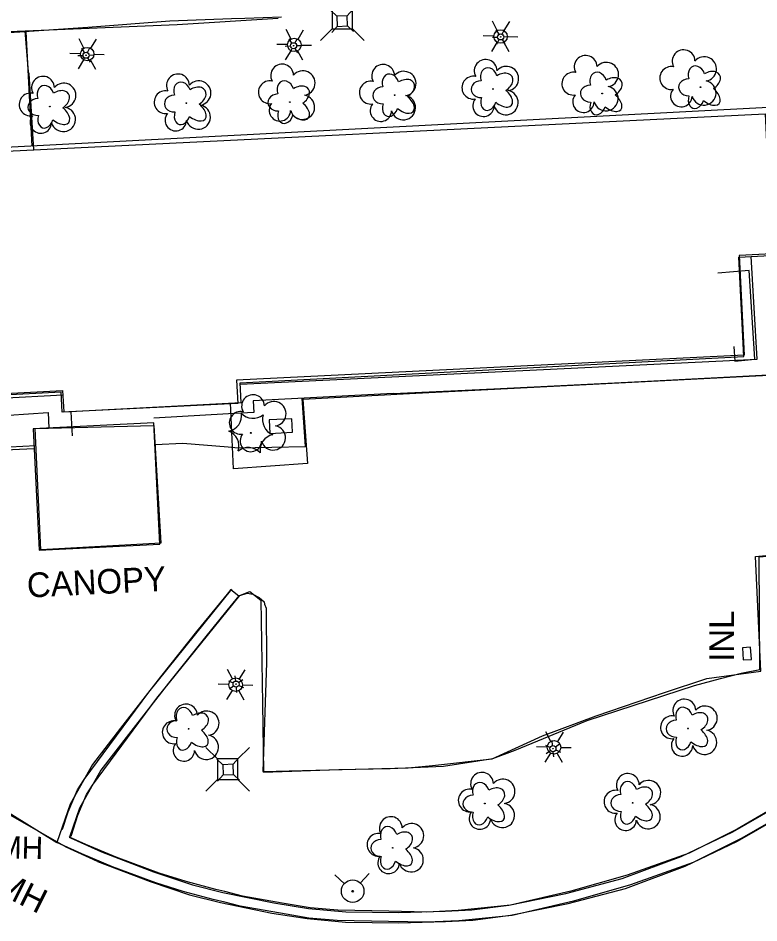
# Model space of a CAD drawing. Extents: x 588843 to 2552415, y 180129 to 269402.
# Drawn here: x 594920.9 to 595101, y 184366.5 to 184586.7 of the extents above; entities that cross this region are included whole.
import ezdxf

# ---------------------------------------------------------------- set-up
doc = ezdxf.new("R2010")
doc.units = 0
for name, color, linetype in [('E_BLD', 7, 'Continuous'), ('E_BLD_HvyDash', 7, 'Continuous'), ('E_BLD_Text', 7, 'Continuous'), ('E_DWY', 7, 'Continuous'), ('E_LAND_Vegetation', 7, 'Continuous'), ('E_LTG', 7, 'Continuous'), ('E_PATH_Sidewalk', 7, 'Continuous'), ('E_RDWY_C_and_G', 7, 'Continuous'), ('E_UTL_AG_Bold', 7, 'Continuous'), ('E_UTL_MH', 7, 'Continuous'), ('E_UTL_MH_Text', 7, 'Continuous'), ('E_UTL_SAN', 7, 'Continuous'), ('E_UTL_WHydrant', 7, 'Continuous'), ('Level 11', 7, 'Continuous'), ('Level 12', 7, 'Continuous'), ('Level 14', 7, 'Continuous'), ('Level 15', 7, 'Continuous'), ('Level 17', 7, 'Continuous'), ('Level 18', 7, 'Continuous'), ('Level 21', 7, 'Continuous')]:
    doc.layers.add(name, color=color, linetype=linetype)

# ---------------------------------------------------------------- blocks, each defined once
blk = doc.blocks.new('MH')
at = {"layer": 'E_UTL_MH'}
for radius in [5, 4, 1.5]:
    blk.add_circle((0, 0), radius, dxfattribs=at)
blk.add_text('MH', height=10.8, dxfattribs=at).set_placement((10, -5.4))
blk = doc.blocks.new('MHT_3')
at = {"layer": 'E_UTL_MH_Text'}
blk.add_text('MH', height=39.37, dxfattribs=at).set_placement((-32.2, -19.7))
blk = doc.blocks.new('LPOL_4')
at = {"layer": 'E_LTG'}
for p, q in [((-13.1, 0), (-4.9, 0)), ((-2.5, 4.3), (-6.6, 11.4)), ((2.5, 4.3), (6.6, 11.4)), ((4.9, 0), (13.1, 0)), ((-6.6, -11.4), (-2.5, -4.3)), ((6.6, -11.4), (2.5, -4.3))]:
    blk.add_line(p, q, dxfattribs=at)
for radius in [4.92, 4.92, 4.92, 0.41]:
    blk.add_circle((0, 0), radius, dxfattribs=at)
blk = doc.blocks.new('PED_3')
at = {"layer": 'E_UTL_AG_Bold'}
for p, q in [((-8.2, 8.2), (-17.5, 17.5)), ((8.2, 8.2), (17.5, 17.5)), ((-8.2, -8.2), (-17.5, -17.5)), ((8.2, -8.2), (17.5, -17.5))]:
    blk.add_line(p, q, dxfattribs=at)
blk.add_lwpolyline([(-8.2, -8.2), (8.2, -8.2), (8.2, 8.2), (-8.2, 8.2)], close=True, dxfattribs=at)
blk = doc.blocks.new('DTRE_4')
at = {"layer": 'E_LAND_Vegetation'}
blk.add_circle((-0.6, 0), 0.601, dxfattribs=at)
for centre, major_axis, ratio in [((-6.1, 17.5), (4.5, -16.3), 0.782863), ((13.3, 9), (-17.3, -9.6), 0.691916), ((-19.3, 0.5), (16.2, -0.4), 0.832022), ((-8.2, -17.2), (5.9, 15.9), 0.716896), ((11.6, -12.2), (-16.4, 15), 0.560249)]:
    blk.add_ellipse(centre, major_axis=major_axis, ratio=ratio, start_param=1.570796, end_param=4.712389, dxfattribs=at)
blk = doc.blocks.new('HYD_3')
at = {"layer": 'E_UTL_WHydrant'}
for p, q in [((-12.6, 12.6), (-27.3, 27.3)), ((12.6, 12.6), (27.3, 27.3))]:
    blk.add_line(p, q, dxfattribs=at)
for radius in [18, 1.38]:
    blk.add_circle((0, 0), radius, dxfattribs=at)
blk = doc.blocks.new('CTRE_4')
at = {"layer": 'E_LAND_Vegetation'}
blk.add_circle((0, 0), 0.733, dxfattribs=at)
for centre, start, end in [((-39.3, 29.4), 280.2067, 5.9716), ((5.9, 49), 220.2113, 305.9762), ((45.4, 19.3), 160.2113, 245.9762), ((-45.4, -19.3), 340.2113, 65.9762), ((39.5, -29.6), 100.2511, 185.9272), ((-5.9, -49), 40.2113, 125.9762)]:
    blk.add_arc(centre, 25.8, start, end, dxfattribs=at)
blk = doc.blocks.new('CANOPY_1')
at = {"layer": 'E_BLD_Text'}
blk.add_text('CANOPY', height=39.37, dxfattribs=at).set_placement((-106.7, -19.7))

msp = doc.modelspace()

# ---------------------------------------------------------------- linework, layer by layer
at = {"layer": 'E_BLD'}
msp.add_lwpolyline([(594931.34, 184495.6), (594915.76, 184494.83), (594915.75, 184495.15), (594887.49, 184493.76), (594884.59, 184552.69), (594913.65, 184554.12), (594912.97, 184554.09), (594984.08, 184557.57), (595102.54, 184563.39), (595104.21, 184529.31), (595096.26, 184528.92), (595097.45, 184504.62), (594974.02, 184498.56), (594974.3, 184492.84), (594931.58, 184490.74)], close=True, dxfattribs=at)
at = {"layer": 'E_BLD_HvyDash'}
for points in [[(594955.54, 184458.88), (594926.41, 184457.28), (594925.02, 184486.76), (594953.9, 184487.5)], [(594953.9, 184487.5), (594955.54, 184458.88)]]:
    msp.add_lwpolyline(points, dxfattribs=at)
at = {"layer": 'E_DWY'}
for points in [[(594853.87, 184578.66), (594856.32, 184579.18), (594875.82, 184580.94), (594916.75, 184583.36), (594959.55, 184585.14), (594984.11, 184586.69)], [(595171.81, 184472.65), (595167.63, 184473.03), (595154.87, 184476.19), (595146.63, 184479.73), (595142.36, 184483.18), (595140.93, 184485.01), (595139.64, 184487.73), (595138.95, 184488.95), (595138.65, 184498.88), (595121.13, 184497.84), (595120.87, 184500.58), (595076.53, 184498.31), (595017.63, 184495.3), (594990.15, 184493.86), (594991.23, 184478.27), (594973.21, 184476.95), (594972.49, 184493.05)], [(594934.07, 184485.02), (594933.77, 184490.85)], [(594881.64, 184488.04), (594882.74, 184475.24), (594890.54, 184477.1), (594890.22, 184480.27), (594909.31, 184481.87), (594925.21, 184482.68)], [(594974.75, 184446.16), (594976.54, 184446.68), (594977.93, 184446.5), (594979.53, 184445.64), (594980.68, 184444.6), (594980.83, 184444.05), (594981.16, 184443.03), (594981.25, 184429.77), (594980.42, 184403.34), (595015.75, 184404.22), (595021.63, 184404.73), (595036.16, 184406.41), (595048.39, 184412.02), (595061.45, 184416.88), (595078.12, 184422.57), (595088.4, 184425.96), (595101.51, 184427.72), (595100.2, 184455.68), (595119.69, 184457.51)], [(594931.59, 184389.19), (594931.65, 184389.24), (594933.03, 184393.52), (594935.28, 184398.87), (594936.9, 184401.38), (594952.64, 184422.65), (594972.81, 184447.72)], [(594933.3, 184387.36), (594933.83, 184387.85), (594935.37, 184392.65), (594937.5, 184397.7), (594938.96, 184399.96), (594954.62, 184421.12), (594974.75, 184446.16)]]:
    msp.add_lwpolyline(points, dxfattribs=at)
at = {"layer": 'E_PATH_Sidewalk'}
for points in [[(594922.53, 184583.6), (594923.28, 184573.61), (594923.48, 184573.24), (594924.59, 184554.66)], [(595094.93, 184506.72), (595095.17, 184503.17), (595100.02, 184503.66), (595098.68, 184525.26), (595091.02, 184524.64)]]:
    msp.add_lwpolyline(points, dxfattribs=at)
at = {"layer": 'E_RDWY_C_and_G'}
for points in [[(594840.99, 184416.47), (594853.52, 184416.52), (594859.86, 184416.05), (594867.1, 184415.1), (594873.59, 184413.68), (594882.4, 184411.05), (594888.77, 184408.67), (594896.76, 184405.03), (594901.36, 184402.7), (594932.46, 184384.96), (594940.08, 184381.5)], [(594941.11, 184383.77), (594953.78, 184378.89), (594963.26, 184375.72), (594970.64, 184373.86), (594983.05, 184371.31), (594991.5, 184369.98), (595000.61, 184369.17), (595013.47, 184368.96), (595024.75, 184369.29), (595031.2, 184369.64), (595040.25, 184370.8), (595054.06, 184373.61), (595067.8, 184377.25), (595082.11, 184382.58), (595094.67, 184388.61), (595108.85, 184396.75)], [(594940.21, 184381.44), (594952.94, 184376.53), (594962.55, 184373.32), (594970.08, 184371.43), (594982.6, 184368.85), (594991.19, 184367.49), (595000.48, 184366.67), (595013.49, 184366.46), (595024.85, 184366.79), (595031.43, 184367.15), (595040.66, 184368.33), (595054.63, 184371.17), (595068.56, 184374.86), (595083.09, 184380.28), (595095.84, 184386.39), (595110.09, 184394.58)], [(594933.3, 184387.36), (594933.6, 184387.18), (594941.11, 184383.77)]]:
    msp.add_lwpolyline(points, dxfattribs=at)
at = {"layer": 'Level 11'}
for points in [[(595163.36, 184448.74), (595157.09, 184440.22), (595149.33, 184431.32), (595142.04, 184423.12), (595133.82, 184415.06), (595127.52, 184409.82), (595118.72, 184402.98), (595108.04, 184396.38), (595095.75, 184389.27), (595084.08, 184383.45), (595069.02, 184378.08), (595055.31, 184374.2), (595040.62, 184370.76), (595027.88, 184369.5), (595020.28, 184369.11), (595011.01, 184369.29)], [(595165.37, 184447.26), (595159.04, 184438.66), (595151.2, 184429.67), (595143.85, 184421.39), (595135.49, 184413.21), (595129.09, 184407.87), (595120.15, 184400.92), (595109.32, 184394.23), (595096.93, 184387.07), (595085.06, 184381.14), (595069.78, 184375.7), (595055.94, 184371.78), (595041.03, 184368.29), (595028.06, 184367), (595020.32, 184366.61), (595010.96, 184366.79)], [(594907.81, 184399.6), (594915.61, 184395.1), (594930.27, 184386.02)], [(594971.15, 184374.06), (594968.95, 184374.6), (594961.73, 184376.51), (594955.19, 184378.6), (594944.7, 184382.47), (594937.33, 184385.53), (594933.37, 184387.34)], [(594971.13, 184371.49), (594968.33, 184372.18), (594961.03, 184374.11), (594954.38, 184376.23), (594943.79, 184380.14), (594936.33, 184383.24), (594930.27, 184386.02)], [(595011.01, 184369.29), (594998.63, 184369.55), (594991.91, 184370.13), (594985.1, 184371.25), (594975.44, 184373), (594971.15, 184374.06)], [(595010.96, 184366.79), (594998.49, 184367.05), (594991.59, 184367.65), (594984.67, 184368.79), (594974.91, 184370.56), (594971.13, 184371.49)]]:
    msp.add_lwpolyline(points, dxfattribs=at)
at = {"layer": 'Level 12'}
for points in [[(595103.37, 184564.96), (594885.16, 184553.5)], [(594888.17, 184493.75), (594931.68, 184496.04), (594931.95, 184490.86), (594975.12, 184493.12), (594974.87, 184497.91), (595097.42, 184504.34), (595096.15, 184528.53), (595105.26, 184529.01), (595103.37, 184564.96)], [(594955.37, 184458.65), (594953.91, 184488.17), (594924.5, 184486.71), (594925.96, 184457.2), (594955.37, 184458.65)]]:
    msp.add_lwpolyline(points, dxfattribs=at)
at = {"layer": 'Level 14'}
for p, q in [((595037.41, 184583.64), (595036.21, 184585.94)), ((595039.11, 184583.63), (595040.48, 184585.86)), ((594987.24, 184581.59), (594986.04, 184583.89)), ((594988.94, 184581.58), (594990.3, 184583.81)), ((594936.87, 184579.36), (594935.67, 184581.67)), ((594938.57, 184579.36), (594939.93, 184581.59)), ((595036.58, 184582.27), (595033.97, 184582.35)), ((595039.85, 184582.18), (595042.37, 184582.12)), ((594986.4, 184580.23), (594983.8, 184580.3)), ((594987.16, 184578.73), (594985.79, 184576.54)), ((594988.79, 184578.69), (594990.04, 184576.51)), ((594989.67, 184580.13), (594992.19, 184580.07)), ((595037.33, 184580.78), (595035.97, 184578.59)), ((595038.97, 184580.74), (595040.21, 184578.56)), ((594936.03, 184578), (594933.43, 184578.07)), ((594936.79, 184576.51), (594935.43, 184574.32)), ((594938.43, 184576.46), (594939.67, 184574.29)), ((594939.31, 184577.91), (594941.83, 184577.84)), ((594973, 184425.86), (594971.8, 184428.16)), ((594974.7, 184425.85), (594976.06, 184428.08)), ((594972.16, 184424.5), (594969.56, 184424.57)), ((594972.92, 184423.01), (594971.55, 184420.82)), ((594974.55, 184422.96), (594975.8, 184420.78)), ((594975.43, 184424.4), (594977.95, 184424.34)), ((595050.42, 184410.63), (595049.22, 184412.93)), ((595052.12, 184410.62), (595053.48, 184412.85)), ((595049.58, 184409.27), (595046.98, 184409.34)), ((595052.85, 184409.18), (595055.37, 184409.11)), ((595050.34, 184407.77), (595048.97, 184405.58)), ((595051.97, 184407.73), (595053.22, 184405.55))]:
    msp.add_line(p, q, dxfattribs=at)
for centre in [(595038.21, 184582.21), (594988.03, 184580.16), (594937.67, 184577.93), (594973.79, 184424.43), (595051.21, 184409.2)]:
    msp.add_circle(centre, 1.64, dxfattribs=at)
at = {"layer": 'Level 15'}
msp.add_lwpolyline([(595097.24, 184430.45), (595099.23, 184430.58), (595099.03, 184433.57), (595097.04, 184433.44), (595097.24, 184430.45)], dxfattribs=at)
at = {"layer": 'Level 17'}
for points in [[(594972.73, 184586.48), (594957.77, 184585.95), (594937.84, 184584.4), (594923.51, 184583.44), (594922.71, 184583.38)], [(594984.94, 184586.91), (594976.02, 184586.59), (594972.73, 184586.48)], [(594922.71, 184583.38), (594918.47, 184583.09)], [(594922.71, 184583.38), (594924.23, 184555.55)], [(594974.89, 184497.57), (595100.64, 184503.68), (595099.19, 184528.69)], [(594885.58, 184527.53), (594883.83, 184527.44), (594884.51, 184512.32), (594885.46, 184492.65), (594889.8, 184492.8), (594900.27, 184493.38), (594916.56, 184494.2), (594931.73, 184494.99)], [(595012.05, 184495.29), (595036.6, 184496.41), (595072.38, 184498.27), (595104.83, 184499.95), (595120.33, 184500.56)], [(595012.05, 184495.29), (594978.05, 184493.55), (594978.22, 184490.73), (594972.02, 184490.36)], [(594971.95, 184482.33), (594974.41, 184482.12), (594990.75, 184482.39), (594989.93, 184494.16)], [(594881.7, 184488.08), (594908.94, 184489.38), (594928.21, 184490.65), (594928.34, 184486.9)], [(594972.02, 184490.36), (594953.86, 184489.3)], [(594881.6, 184488.08), (594882.22, 184475.83), (594887.46, 184475.97), (594901.97, 184479.52), (594915.88, 184481.51), (594924.74, 184481.94)], [(594954.17, 184482.9), (594960.93, 184483.25), (594971.95, 184482.33)], [(595011.37, 184404.06), (595024.33, 184404.64), (595036.32, 184406.45), (595041.77, 184408.54), (595059.27, 184415.7), (595085.4, 184424.21), (595091.69, 184425.93), (595096.76, 184427.27), (595101.28, 184428.15), (595101.08, 184455.57), (595125.34, 184457.55), (595131.15, 184457.75), (595134.71, 184457.86), (595138.62, 184457.22), (595146.3, 184455.29), (595160.03, 184451.56), (595162.59, 184449.88), (595163.36, 184448.74)], [(594972.63, 184447.62), (594971.69, 184446.47)], [(594972.63, 184447.62), (594974.56, 184446.03)], [(594974.56, 184446.03), (594977.23, 184447.11), (594979.89, 184444.98), (594980.27, 184419.83), (594980.58, 184403.18), (594998.87, 184403.78), (595011.37, 184404.06)], [(594971.69, 184446.47), (594964.25, 184437.37), (594955.52, 184426.32), (594945.76, 184413.85), (594938.93, 184405.04), (594933.52, 184395.39), (594930.27, 184386.02)], [(594974.56, 184446.03), (594971.66, 184442.48)], [(594971.66, 184442.48), (594966.2, 184435.8), (594957.48, 184424.78), (594947.73, 184412.32), (594941.02, 184403.65), (594935.81, 184394.36), (594933.37, 184387.34)]]:
    msp.add_lwpolyline(points, dxfattribs=at)
at = {"layer": 'Level 18'}
for centre, radius, start, end in [((595082.72, 184576.18), 2.78, 1.3946, 209.1675), ((595034.59, 184573.82), 2.78, 1.3946, 209.1675), ((595058.91, 184574.81), 2.78, 1.3946, 209.1675), ((595087.76, 184574.32), 2.97, 278.4237, 139.6575), ((594985.08, 184572.72), 2.78, 1.3946, 209.1675), ((595009.64, 184572.63), 2.78, 1.3946, 209.1675), ((595039.64, 184571.97), 2.97, 278.4237, 139.6575), ((595063.95, 184572.95), 2.97, 278.4237, 139.6575), ((595079.72, 184572.1), 2.78, 78.0716, 279.0826), ((594926.91, 184569.73), 2.78, 1.3946, 209.1675), ((594959.74, 184570.3), 2.78, 1.3946, 209.1675), ((594990.12, 184570.86), 2.97, 278.4237, 139.6575), ((595014.68, 184570.77), 2.97, 278.4237, 139.6575), ((595031.59, 184569.75), 2.78, 78.0716, 279.0826), ((595055.91, 184570.73), 2.78, 78.0716, 279.0826), ((594931.95, 184567.88), 2.97, 278.4237, 139.6575), ((594964.78, 184568.44), 2.97, 278.4237, 139.6575), ((594982.08, 184568.64), 2.78, 78.0716, 279.0826), ((595006.64, 184568.55), 2.78, 78.0716, 279.0826), ((595063.84, 184567.09), 2.97, 196.0745, 79.0477), ((595087.65, 184568.47), 2.97, 196.0745, 79.0477), ((594923.91, 184565.66), 2.78, 78.0716, 279.0826), ((594956.74, 184566.22), 2.78, 78.0716, 279.0826), ((594990.01, 184565.01), 2.97, 196.0745, 79.0477), ((595014.57, 184564.91), 2.97, 196.0745, 79.0477), ((595039.53, 184566.11), 2.97, 196.0745, 79.0477), ((595058.37, 184566.33), 2.61, 140.7797, 358.7123), ((595082.18, 184567.7), 2.61, 140.7797, 358.7123), ((594964.67, 184562.59), 2.97, 196.0745, 79.0477), ((594984.54, 184564.24), 2.61, 140.7797, 358.7123), ((595009.1, 184564.15), 2.61, 140.7797, 358.7123), ((595034.06, 184565.35), 2.61, 140.7797, 358.7123), ((594931.84, 184562.02), 2.97, 196.0745, 79.0477), ((594959.2, 184561.83), 2.61, 140.7797, 358.7123), ((594926.37, 184561.26), 2.61, 140.7797, 358.7123), ((594978.01, 184492.24), 2.78, 1.3946, 209.1675), ((594983.06, 184490.38), 2.97, 278.4237, 139.6575), ((594975.01, 184488.16), 2.78, 78.0716, 279.0826), ((594982.94, 184484.52), 2.97, 196.0745, 79.0477), ((594977.47, 184483.76), 2.61, 140.7797, 358.7123), ((595082.9, 184418.14), 2.78, 1.3946, 209.1675), ((594961.71, 184416.93), 2.78, 1.3946, 209.1675), ((594966.76, 184415.07), 2.97, 278.4237, 139.6575), ((595087.94, 184416.28), 2.97, 278.4237, 139.6575), ((595079.9, 184414.06), 2.78, 78.0716, 279.0826), ((594958.71, 184412.85), 2.78, 78.0716, 279.0826), ((594966.65, 184409.21), 2.97, 196.0745, 79.0477), ((595082.36, 184409.66), 2.61, 140.7797, 358.7123), ((595087.83, 184410.43), 2.97, 196.0745, 79.0477), ((594961.18, 184408.45), 2.61, 140.7797, 358.7123), ((595033.71, 184400.32), 2.78, 1.3946, 209.1675), ((595069.16, 184400.03), 2.78, 1.3946, 209.1675), ((595038.75, 184398.47), 2.97, 278.4237, 139.6575), ((595074.2, 184398.17), 2.97, 278.4237, 139.6575), ((595030.71, 184396.25), 2.78, 78.0716, 279.0826), ((595066.16, 184395.95), 2.78, 78.0716, 279.0826), ((595038.64, 184392.61), 2.97, 196.0745, 79.0477), ((595074.09, 184392.32), 2.97, 196.0745, 79.0477), ((595011.52, 184389.53), 2.78, 1.3946, 209.1675), ((595033.17, 184391.85), 2.61, 140.7797, 358.7123), ((595068.62, 184391.55), 2.61, 140.7797, 358.7123), ((595016.56, 184387.67), 2.97, 278.4237, 139.6575), ((595008.52, 184385.46), 2.78, 78.0716, 279.0826), ((595010.98, 184381.06), 2.61, 140.7797, 358.7123), ((595016.45, 184381.82), 2.97, 196.0745, 79.0477)]:
    msp.add_arc(centre, radius, start, end, dxfattribs=at)
at = {"layer": 'Level 21'}
for p, q in [((594997.22, 184584.05), (594994.39, 184581.23)), ((595002.22, 184584.05), (595005.05, 184581.23)), ((594969.33, 184406.36), (594966.5, 184409.19)), ((594974.33, 184406.36), (594977.16, 184409.19)), ((594969.33, 184401.36), (594966.5, 184398.53)), ((594974.33, 184401.36), (594977.16, 184398.53))]:
    msp.add_line(p, q, dxfattribs=at)
for points in [[(594997.22, 184584.05), (595002.22, 184584.05), (595002.22, 184589.05), (594997.22, 184589.05)], [(594969.33, 184401.36), (594974.33, 184401.36), (594974.33, 184406.36), (594969.33, 184406.36)]]:
    msp.add_lwpolyline(points, close=True, dxfattribs=at)
msp.add_lwpolyline([(594982.09, 184485.61), (594987.6, 184485.87), (594987.45, 184489.14), (594981.94, 184488.88), (594982.09, 184485.61)], dxfattribs=at)

# ---------------------------------------------------------------- block references
at = {"layer": 'E_BLD_Text', "xscale": 0.15240030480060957, "yscale": 0.1524003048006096, "rotation": 2.834815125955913}
msp.add_blockref('CANOPY_1', (594939.23, 184449.43), dxfattribs=at)
at = {"layer": 'E_LAND_Vegetation', "yscale": 0.15240030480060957}
for name, p, xscale, rotation in [('DTRE_4', (595036.45, 184569.43), 0.1524003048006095, 2.3276622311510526), ('DTRE_4', (595086.94, 184569.88), 0.1524003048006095, 2.3276622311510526), ('DTRE_4', (594987.02, 184566.26), 0.15240030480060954, 3.4338469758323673), ('DTRE_4', (595012.54, 184567.92), 0.1524003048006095, 2.3276622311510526), ('DTRE_4', (595063.03, 184568.36), 0.1524003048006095, 2.3276622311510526), ('DTRE_4', (594928.65, 184565.15), 0.15240030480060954, 3.4338469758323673), ('DTRE_4', (594961.86, 184565.99), 0.15240030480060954, 3.4338469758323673), ('CTRE_4', (594977.44, 184485.72), 0.1524003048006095, 2.3276622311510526), ('DTRE_4', (594962.42, 184413.71), 0.1524003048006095, 2.3276622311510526), ('DTRE_4', (595083.9, 184413.78), 0.1524003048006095, 2.3276622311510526), ('DTRE_4', (595034.47, 184395.5), 0.1524003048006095, 2.3276622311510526), ('DTRE_4', (595070.43, 184395.7), 0.1524003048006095, 2.3276622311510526), ('DTRE_4', (595012.07, 184384.74), 0.1524003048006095, 2.3276622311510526)]:
    msp.add_blockref(name, p, dxfattribs=dict(at, xscale=xscale, rotation=rotation))
at = {"layer": 'E_LTG'}
for p, xscale, yscale, rotation in [((595038.25, 184582.11), 0.1524003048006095, 0.15240030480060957, 2.3276622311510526), ((594987.85, 184579.95), 0.1524003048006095, 0.15240030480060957, 2.3276622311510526), ((594937.4, 184577.65), 0.1524003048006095, 0.15240030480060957, 2.3276622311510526), ((594973.89, 184424.57), 0.1524003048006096, 0.1524003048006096, -24.21972835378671), ((595050.94, 184408.86), 0.1524003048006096, 0.1524003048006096, -24.21972835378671)]:
    msp.add_blockref('LPOL_4', p, dxfattribs=dict(at, xscale=xscale, yscale=yscale, rotation=rotation))
at = {"layer": 'E_UTL_AG_Bold', "xscale": 0.1524003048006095, "yscale": 0.15240030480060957, "rotation": 2.3276622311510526}
for p in [(594999.69, 184585.97), (594971.95, 184403.76)]:
    msp.add_blockref('PED_3', p, dxfattribs=at)
at = {"layer": 'E_UTL_MH_Text', "xscale": 0.15240030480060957, "yscale": 0.1524003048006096, "rotation": -26.610656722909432}
msp.add_blockref('MHT_3', (594920.49, 184374.66), dxfattribs=at)
at = {"layer": 'E_UTL_SAN', "xscale": 0.500001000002, "yscale": 0.5000010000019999, "rotation": -1.2027594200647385}
msp.add_blockref('MH', (594910.73, 184385.03), dxfattribs=at)
at = {"layer": 'E_UTL_WHydrant', "xscale": 0.1524003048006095, "yscale": 0.15240030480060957, "rotation": 2.3276622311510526}
msp.add_blockref('HYD_3', (595002.24, 184374.16), dxfattribs=at)

# ---------------------------------------------------------------- texts
at = {"layer": 'Level 15'}
msp.add_text('INL', height=6, rotation=90, dxfattribs=at).set_placement((595094.99, 184430))

doc.saveas('drawing.dxf')
